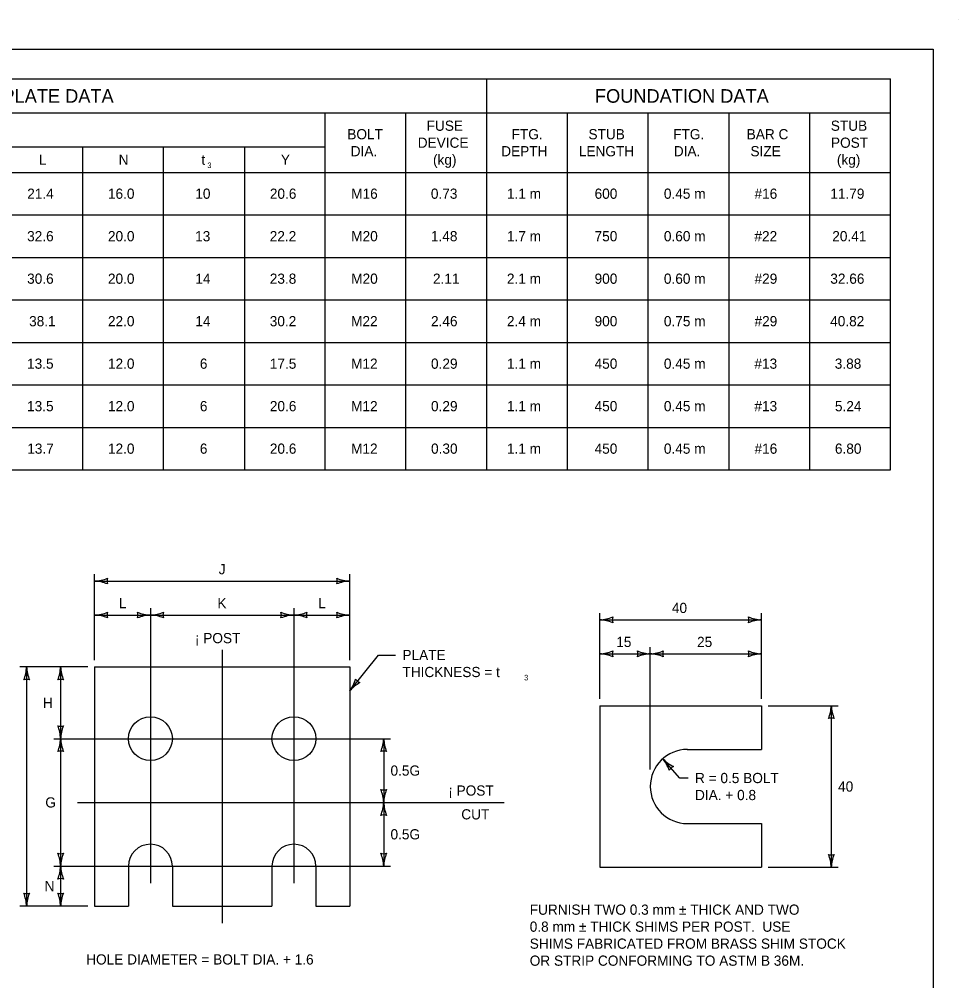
# Model space of a CAD drawing. Extents: x 49991.4 to 50021, y 49987.6 to 50011.4.
# Drawn here: x 50011.38 to 50016.9, y 49993.52 to 49999.18 of the extents above; entities that cross this region are included whole.
import ezdxf

# ---------------------------------------------------------------- set-up
doc = ezdxf.new("R2010")
doc.units = 0
for name, color, linetype in [('Level 1', 7, 'Continuous'), ('Level 2', 7, 'Continuous'), ('Level 3', 7, 'Continuous'), ('Level 5', 7, 'Continuous')]:
    doc.layers.add(name, color=color, linetype=linetype)

msp = doc.modelspace()

# ---------------------------------------------------------------- linework, layer by layer
at = {"layer": 'Level 1'}
for p, q in [((50016.9001, 49999.1756), (50016.9001, 49999.1756)), ((50011.8184, 49995.3646), (50013.3184, 49995.3646)), ((50011.8184, 49995.3646), (50011.8184, 49993.9584)), ((50013.3184, 49995.3646), (50013.3184, 49993.9584)), ((50014.7891, 49995.1367), (50015.7397, 49995.1367)), ((50014.7891, 49995.1367), (50014.7891, 49994.1863)), ((50015.7397, 49995.1367), (50015.7397, 49994.8792)), ((50015.3039, 49994.8792), (50015.7397, 49994.8792)), ((50015.3039, 49994.4438), (50015.7397, 49994.4438)), ((50015.7397, 49994.4438), (50015.7397, 49994.1863)), ((50012.0176, 49994.1928), (50012.0176, 49993.9584)), ((50012.2754, 49994.1928), (50012.2754, 49993.9584)), ((50012.8614, 49994.1928), (50012.8614, 49993.9584)), ((50013.1192, 49994.1928), (50013.1192, 49993.9584)), ((50014.7891, 49994.1863), (50015.7397, 49994.1863)), ((50011.8184, 49993.9584), (50012.0176, 49993.9584)), ((50012.2754, 49993.9584), (50012.8614, 49993.9584)), ((50013.1192, 49993.9584), (50013.3184, 49993.9584))]:
    msp.add_line(p, q, dxfattribs=at)
msp.add_lwpolyline([(49999.3835, 49998.9992), (50016.7501, 49998.9992), (50016.7501, 49987.7988), (49999.3835, 49987.7988)], close=True, dxfattribs=at)
for centre in [(50012.1466, 49994.9428), (50012.9903, 49994.9428)]:
    msp.add_circle(centre, 0.1289, dxfattribs=at)
for centre, radius, start, end in [((50015.3041, 49994.6615), 0.2179, 90, 270), ((50012.1466, 49994.1928), 0.1289, 0, 180), ((50012.9903, 49994.1928), 0.1289, 0, 180)]:
    msp.add_arc(centre, radius, start, end, dxfattribs=at)
at = {"layer": 'Level 2'}
for p, q in [((50002.7742, 49998.8242), (50016.4992, 49998.8242)), ((50014.1242, 49996.5242), (50014.1242, 49998.8242)), ((50016.4992, 49996.5242), (50016.4992, 49998.8242)), ((50002.7742, 49998.6242), (50016.4992, 49998.6242)), ((50013.1742, 49996.5242), (50013.1742, 49998.6242)), ((50013.6492, 49996.5242), (50013.6492, 49998.6242)), ((50014.5992, 49996.5242), (50014.5992, 49998.6242)), ((50015.0742, 49996.5242), (50015.0742, 49998.6242)), ((50015.5492, 49996.5242), (50015.5492, 49998.6242)), ((50016.0242, 49996.5242), (50016.0242, 49998.6242)), ((50008.8992, 49998.4242), (50013.1742, 49998.4242)), ((50011.7492, 49996.5242), (50011.7492, 49998.4242)), ((50012.2242, 49996.5242), (50012.2242, 49998.4242)), ((50012.2242, 49996.5242), (50012.2242, 49998.4242)), ((50012.6992, 49998.4242), (50012.6992, 49996.5242)), ((50002.7742, 49998.2742), (50016.4992, 49998.2742)), ((50004.9742, 49998.0242), (50016.4992, 49998.0242)), ((50002.7742, 49997.7742), (50016.4992, 49997.7742)), ((50004.9742, 49997.5242), (50016.4992, 49997.5242)), ((50002.7742, 49997.2742), (50016.4992, 49997.2742)), ((50004.9742, 49997.0242), (50016.4992, 49997.0242)), ((50002.7742, 49996.7742), (50016.4992, 49996.7742)), ((50002.7742, 49996.5242), (50016.4992, 49996.5242))]:
    msp.add_line(p, q, dxfattribs=at)
at = {"layer": 'Level 3'}
for p, q in [((50011.8184, 49995.4046), (50011.8184, 49995.91)), ((50011.8184, 49995.87), (50013.3184, 49995.87)), ((50013.3184, 49995.4046), (50013.3184, 49995.91)), ((50011.8184, 49995.67), (50012.1466, 49995.67)), ((50012.1466, 49995.67), (50012.9904, 49995.67)), ((50012.9904, 49995.67), (50013.3184, 49995.67)), ((50014.7891, 49995.1767), (50014.7891, 49995.6821)), ((50014.7891, 49995.6421), (50015.7397, 49995.6421)), ((50015.7397, 49995.1767), (50015.7397, 49995.6821)), ((50015.0862, 49994.7615), (50015.0862, 49995.4821)), ((50013.3184, 49995.2237), (50013.487, 49995.4351)), ((50013.487, 49995.4351), (50013.5886, 49995.4351)), ((50014.7891, 49995.4421), (50015.0862, 49995.4421)), ((50015.0862, 49995.4421), (50015.7397, 49995.4421)), ((50011.7784, 49995.3646), (50011.3784, 49995.3646)), ((50011.4184, 49995.3646), (50011.4184, 49993.9584)), ((50011.6184, 49995.3646), (50011.6184, 49994.9428)), ((50015.7797, 49995.1367), (50016.1904, 49995.1367)), ((50016.1504, 49995.1367), (50016.1504, 49994.1863)), ((50011.6184, 49994.9428), (50011.6184, 49994.1928)), ((50013.5184, 49994.9428), (50013.5184, 49994.5678)), ((50015.2598, 49994.7114), (50015.1599, 49994.8248)), ((50015.3091, 49994.7114), (50015.2598, 49994.7114)), ((50013.5184, 49994.5678), (50013.5184, 49994.1928)), ((50011.6184, 49994.1928), (50011.6184, 49993.9584)), ((50015.7797, 49994.1863), (50016.1904, 49994.1863)), ((50011.7784, 49993.9584), (50011.3784, 49993.9584))]:
    msp.add_line(p, q, dxfattribs=at)
for centre, radius, start, end in [((50011.8069, 49996.1027), 0.233, 272.8273, 292.0772), ((50011.8092, 49995.6479), 0.2223, 67.456, 87.6395), ((50011.9466, 49995.87), 0.0548, 162.1388, 197.8612), ((50013.3276, 49996.0921), 0.2223, 247.456, 267.6395), ((50013.1902, 49995.87), 0.0548, 342.1388, 17.8612), ((50013.3299, 49995.6373), 0.233, 92.8273, 112.0772), ((50011.8069, 49995.9027), 0.233, 272.8273, 292.0772), ((50011.8092, 49995.4479), 0.2223, 67.456, 87.6395), ((50011.9466, 49995.67), 0.0548, 162.1388, 197.8612), ((50012.1558, 49995.8921), 0.2223, 247.456, 267.6395), ((50012.0184, 49995.67), 0.0548, 342.1388, 17.8612), ((50012.1581, 49995.4373), 0.233, 92.8273, 112.0772), ((50012.1351, 49995.9027), 0.233, 272.8273, 292.0772), ((50012.1374, 49995.4479), 0.2223, 67.456, 87.6395), ((50012.2748, 49995.67), 0.0548, 162.1388, 197.8612), ((50012.9996, 49995.8921), 0.2223, 247.456, 267.6395), ((50012.8622, 49995.67), 0.0548, 342.1388, 17.8612), ((50013.0019, 49995.4373), 0.233, 92.8273, 112.0772), ((50012.9789, 49995.9027), 0.233, 272.8273, 292.0772), ((50012.9812, 49995.4479), 0.2223, 67.456, 87.6395), ((50013.1186, 49995.67), 0.0548, 162.1388, 197.8612), ((50013.3276, 49995.8921), 0.2223, 247.456, 267.6395), ((50013.1902, 49995.67), 0.0548, 342.1388, 17.8612), ((50013.3299, 49995.4373), 0.233, 92.8273, 112.0772), ((50014.7776, 49995.8748), 0.233, 272.8273, 292.0772), ((50014.7799, 49995.42), 0.2223, 67.456, 87.6395), ((50014.9173, 49995.6421), 0.0548, 162.1388, 197.8612), ((50015.7489, 49995.8642), 0.2223, 247.456, 267.6395), ((50015.6115, 49995.6421), 0.0548, 342.1388, 17.8612), ((50015.7512, 49995.4094), 0.233, 92.8273, 112.0772), ((50014.7776, 49995.6748), 0.233, 272.8273, 292.0772), ((50014.7799, 49995.22), 0.2223, 67.456, 87.6395), ((50014.9173, 49995.4421), 0.0548, 162.1388, 197.8612), ((50015.0954, 49995.6642), 0.2223, 247.456, 267.6395), ((50014.958, 49995.4421), 0.0548, 342.1388, 17.8612), ((50015.0977, 49995.2094), 0.233, 92.8273, 112.0772), ((50015.0747, 49995.6748), 0.233, 272.8273, 292.0772), ((50015.077, 49995.22), 0.2223, 67.456, 87.6395), ((50015.2144, 49995.4421), 0.0548, 162.1388, 197.8612), ((50015.7489, 49995.6642), 0.2223, 247.456, 267.6395), ((50015.6115, 49995.4421), 0.0548, 342.1388, 17.8612), ((50015.7512, 49995.2094), 0.233, 92.8273, 112.0772), ((50011.1963, 49995.3738), 0.2223, 337.456, 357.6395), ((50011.6511, 49995.3761), 0.233, 182.8273, 202.0772), ((50011.3963, 49995.3738), 0.2223, 337.456, 357.6395), ((50011.8511, 49995.3761), 0.233, 182.8273, 202.0772), ((50011.4184, 49995.2364), 0.0548, 72.1388, 107.8612), ((50011.6184, 49995.2364), 0.0548, 72.1388, 107.8612), ((50013.1293, 49995.3598), 0.233, 324.2506, 343.5004), ((50013.4863, 49995.078), 0.2223, 118.8793, 139.0628), ((50013.3983, 49995.3239), 0.0548, 213.5621, 249.2845), ((50015.9283, 49995.1459), 0.2223, 337.456, 357.6395), ((50016.3831, 49995.1482), 0.233, 182.8273, 202.0772), ((50011.6184, 49995.071), 0.0548, 252.1388, 287.8612), ((50011.3857, 49994.9313), 0.233, 2.8273, 22.0772), ((50011.8405, 49994.9336), 0.2223, 157.456, 177.6395), ((50016.1504, 49995.0085), 0.0548, 72.1388, 107.8612), ((50011.3963, 49994.952), 0.2223, 337.456, 357.6395), ((50011.8511, 49994.9543), 0.233, 182.8273, 202.0772), ((50013.2963, 49994.952), 0.2223, 337.456, 357.6395), ((50013.7511, 49994.9543), 0.233, 182.8273, 202.0772), ((50011.6184, 49994.8146), 0.0548, 72.1388, 107.8612), ((50013.5184, 49994.8146), 0.0548, 72.1388, 107.8612), ((50014.9872, 49994.6848), 0.2223, 18.8449, 39.0284), ((50015.3269, 49994.9873), 0.233, 224.2162, 243.466), ((50015.2447, 49994.7286), 0.0548, 113.5277, 149.25), ((50013.5184, 49994.696), 0.0548, 252.1388, 287.8612), ((50013.2857, 49994.5563), 0.233, 2.8273, 22.0772), ((50013.7405, 49994.5586), 0.2223, 157.456, 177.6395), ((50013.2963, 49994.577), 0.2223, 337.456, 357.6395), ((50013.7511, 49994.5793), 0.233, 182.8273, 202.0772), ((50013.5184, 49994.4396), 0.0548, 72.1388, 107.8612), ((50011.6184, 49994.321), 0.0548, 252.1388, 287.8612), ((50011.3857, 49994.1813), 0.233, 2.8273, 22.0772), ((50011.8405, 49994.1836), 0.2223, 157.456, 177.6395), ((50013.5184, 49994.321), 0.0548, 252.1388, 287.8612), ((50013.2857, 49994.1813), 0.233, 2.8273, 22.0772), ((50013.7405, 49994.1836), 0.2223, 157.456, 177.6395), ((50016.1504, 49994.3145), 0.0548, 252.1388, 287.8612), ((50015.9177, 49994.1748), 0.233, 2.8273, 22.0772), ((50016.3725, 49994.1771), 0.2223, 157.456, 177.6395), ((50011.3963, 49994.202), 0.2223, 337.456, 357.6395), ((50011.8511, 49994.2043), 0.233, 182.8273, 202.0772), ((50011.6184, 49994.0646), 0.0548, 72.1388, 107.8612), ((50011.4184, 49994.0866), 0.0548, 252.1388, 287.8612), ((50011.1857, 49993.9469), 0.233, 2.8273, 22.0772), ((50011.6405, 49993.9492), 0.2223, 157.456, 177.6395), ((50011.6184, 49994.0866), 0.0548, 252.1388, 287.8612), ((50011.3857, 49993.9469), 0.233, 2.8273, 22.0772), ((50011.8405, 49993.9492), 0.2223, 157.456, 177.6395)]:
    msp.add_arc(centre, radius, start, end, dxfattribs=at)
at = {"layer": 'Level 5'}
for p, q in [((50012.1466, 49995.71), (50012.1466, 49994.0928)), ((50012.9904, 49995.71), (50012.9904, 49994.0928)), ((50012.5684, 49995.4646), (50012.5684, 49993.8584)), ((50011.5784, 49994.9428), (50013.5584, 49994.9428)), ((50011.7184, 49994.5678), (50014.2276, 49994.5678)), ((50011.5784, 49994.1928), (50013.5584, 49994.1928))]:
    msp.add_line(p, q, dxfattribs=at)

# ---------------------------------------------------------------- texts
at = {"layer": 'Level 2'}
for s, height, p in [('FUSE PLATE DATA', 0.08, (50010.9615, 49998.6842)), ('FOUNDATION DATA', 0.08, (50014.7606, 49998.6842)), ('FUSE', 0.06, (50013.7708, 49998.5192)), ('STUB', 0.06, (50016.1475, 49998.5192)), ('BOLT', 0.06, (50013.3043, 49998.4692)), ('FTG.', 0.06, (50014.2706, 49998.4692)), ('STUB', 0.06, (50014.7225, 49998.4692)), ('FTG.', 0.06, (50015.2206, 49998.4692)), ('BAR C', 0.06, (50015.6529, 49998.4692)), ('DEVICE', 0.06, (50013.7184, 49998.4192)), ('POST', 0.06, (50016.1486, 49998.4192)), ('DIA.', 0.06, (50013.3243, 49998.3692)), ('DEPTH', 0.06, (50014.2094, 49998.3692)), ('LENGTH', 0.06, (50014.6658, 49998.3692)), ('DIA.', 0.06, (50015.2243, 49998.3692)), ('SIZE', 0.06, (50015.6752, 49998.3692)), ('L', 0.06, (50011.4905, 49998.3192)), ('N', 0.06, (50011.9596, 49998.3192)), ('t', 0.06, (50012.4461, 49998.3192)), ('Y', 0.06, (50012.9139, 49998.3192)), ('(kg)', 0.06, (50013.8083, 49998.3192)), ('(kg)', 0.06, (50016.1833, 49998.3192)), ('3', 0.0325, (50012.4815, 49998.3)), ('21.4', 0.06, (50011.422, 49998.1192)), ('16.0', 0.06, (50011.8967, 49998.1192)), ('10', 0.06, (50012.4104, 49998.1192)), ('20.6', 0.06, (50012.8488, 49998.1192)), ('M16', 0.06, (50013.3272, 49998.1192)), ('0.73', 0.06, (50013.7958, 49998.1192)), ('1.1 m', 0.06, (50014.243, 49998.1192)), ('600', 0.06, (50014.7585, 49998.1192)), ('0.45 m', 0.06, (50015.166, 49998.1192)), ('#16', 0.06, (50015.699, 49998.1192)), ('11.79', 0.06, (50016.1446, 49998.1192)), ('32.6', 0.06, (50011.4215, 49997.8692)), ('20.0', 0.06, (50011.8967, 49997.8692)), ('13', 0.06, (50012.4096, 49997.8692)), ('22.2', 0.06, (50012.8482, 49997.8692)), ('M20', 0.06, (50013.3273, 49997.8692)), ('1.48', 0.06, (50013.796, 49997.8692)), ('1.7 m', 0.06, (50014.243, 49997.8692)), ('750', 0.06, (50014.7585, 49997.8692)), ('0.60 m', 0.06, (50015.166, 49997.8692)), ('#22', 0.06, (50015.6983, 49997.8692)), ('20.41', 0.06, (50016.1561, 49997.8692)), ('30.6', 0.06, (50011.4215, 49997.6192)), ('20.0', 0.06, (50011.8967, 49997.6192)), ('14', 0.06, (50012.4108, 49997.6192)), ('23.8', 0.06, (50012.8484, 49997.6192)), ('M20', 0.06, (50013.3273, 49997.6192)), ('2.11', 0.06, (50013.8081, 49997.6192)), ('2.1 m', 0.06, (50014.243, 49997.6192)), ('900', 0.06, (50014.7585, 49997.6192)), ('0.60 m', 0.06, (50015.166, 49997.6192)), ('#29', 0.06, (50015.699, 49997.6192)), ('32.66', 0.06, (50016.1446, 49997.6192)), ('38.1', 0.06, (50011.4331, 49997.3692)), ('22.0', 0.06, (50011.8967, 49997.3692)), ('14', 0.06, (50012.4108, 49997.3692)), ('30.2', 0.06, (50012.8483, 49997.3692)), ('M22', 0.06, (50013.3265, 49997.3692)), ('2.46', 0.06, (50013.7965, 49997.3692)), ('2.4 m', 0.06, (50014.243, 49997.3692)), ('900', 0.06, (50014.7585, 49997.3692)), ('0.75 m', 0.06, (50015.166, 49997.3692)), ('#29', 0.06, (50015.699, 49997.3692)), ('40.82', 0.06, (50016.1439, 49997.3692)), ('13.5', 0.06, (50011.4211, 49997.1192)), ('12.0', 0.06, (50011.8967, 49997.1192)), ('6', 0.06, (50012.4372, 49997.1192)), ('17.5', 0.06, (50012.8485, 49997.1192)), ('M12', 0.06, (50013.3265, 49997.1192)), ('0.29', 0.06, (50013.7965, 49997.1192)), ('1.1 m', 0.06, (50014.243, 49997.1192)), ('450', 0.06, (50014.7585, 49997.1192)), ('0.45 m', 0.06, (50015.166, 49997.1192)), ('#13', 0.06, (50015.6983, 49997.1192)), ('3.88', 0.06, (50016.171, 49997.1192)), ('13.5', 0.06, (50011.4211, 49996.8692)), ('12.0', 0.06, (50011.8967, 49996.8692)), ('6', 0.06, (50012.4372, 49996.8692)), ('20.6', 0.06, (50012.8488, 49996.8692)), ('M12', 0.06, (50013.3265, 49996.8692)), ('0.29', 0.06, (50013.7965, 49996.8692)), ('1.1 m', 0.06, (50014.243, 49996.8692)), ('450', 0.06, (50014.7585, 49996.8692)), ('0.45 m', 0.06, (50015.166, 49996.8692)), ('#13', 0.06, (50015.6983, 49996.8692)), ('5.24', 0.06, (50016.172, 49996.8692)), ('13.7', 0.06, (50011.4222, 49996.6192)), ('12.0', 0.06, (50011.8967, 49996.6192)), ('6', 0.06, (50012.4372, 49996.6192)), ('20.6', 0.06, (50012.8488, 49996.6192)), ('M12', 0.06, (50013.3265, 49996.6192)), ('0.30', 0.06, (50013.7967, 49996.6192)), ('1.1 m', 0.06, (50014.243, 49996.6192)), ('450', 0.06, (50014.7585, 49996.6192)), ('0.45 m', 0.06, (50015.166, 49996.6192)), ('#16', 0.06, (50015.699, 49996.6192)), ('6.80', 0.06, (50016.1717, 49996.6192)), ('J', 0.06, (50012.5481, 49995.91)), ('L', 0.06, (50011.9613, 49995.71)), ('K', 0.06, (50012.5404, 49995.71)), ('L', 0.06, (50013.1332, 49995.71)), ('40', 0.06, (50015.2131, 49995.6821)), ('¡ POST', 0.06, (50012.4082, 49995.5046)), ('15', 0.06, (50014.8858, 49995.4821)), ('25', 0.06, (50015.3612, 49995.4821)), ('PLATE', 0.06, (50013.6286, 49995.4051)), ('THICKNESS = t', 0.06, (50013.6286, 49995.3051)), ('3', 0.0325, (50014.3443, 49995.2859)), ('H', 0.06, (50011.5144, 49995.1237)), ('0.5G', 0.06, (50013.5584, 49994.7253)), ('R = 0.5 BOLT', 0.06, (50015.3491, 49994.6814)), ('40', 0.06, (50016.1904, 49994.6315)), ('¡ POST', 0.06, (50013.898, 49994.6078)), ('DIA. + 0.8', 0.06, (50015.3491, 49994.5814)), ('G', 0.06, (50011.5286, 49994.5378)), ('CUT', 0.06, (50013.9746, 49994.4678)), ('0.5G', 0.06, (50013.5584, 49994.3503)), ('N', 0.06, (50011.5241, 49994.0456)), ('FURNISH TWO 0.3 mm ± THICK AND TWO', 0.06, (50014.3771, 49993.9069)), ('0.8 mm ± THICK SHIMS PER POST.  USE', 0.06, (50014.3771, 49993.8069)), ('SHIMS FABRICATED FROM BRASS SHIM STOCK', 0.06, (50014.3771, 49993.7069)), ('HOLE DIAMETER = BOLT DIA. + 1.6', 0.06, (50011.7688, 49993.6141)), ('OR STRIP CONFORMING TO ASTM B 36M.', 0.06, (50014.3771, 49993.6069))]:
    msp.add_text(s, height=height, dxfattribs=at).set_placement(p)

doc.saveas('drawing.dxf')
